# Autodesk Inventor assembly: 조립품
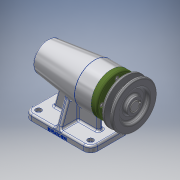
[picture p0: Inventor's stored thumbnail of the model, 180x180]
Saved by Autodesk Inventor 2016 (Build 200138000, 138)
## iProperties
Created: 2018-09
Part Number: 조립품
Document SubType Name: Assembly
Designer: CAMTIC
Author: CAMTIC
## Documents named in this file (12)
- C:\Users\CAMTIC\Desktop\480907V1023\조립품.iam
- C:\Users\CAMTIC\Desktop\480907V1023\본체.ipt
- C:\Users\CAMTIC\Desktop\480907V1023\베어링 51202.ipt
- C:\Users\CAMTIC\Desktop\480907V1023\어댑터슬리브.ipt
- C:\Users\CAMTIC\Desktop\480907V1023\베어링 6004.ipt
- C:\Users\CAMTIC\Desktop\480907V1023\축.ipt
- C:\Users\CAMTIC\Desktop\480907V1023\볼트 M4.ipt
- C:\Users\CAMTIC\Desktop\480907V1023\커버.ipt
- C:\Users\CAMTIC\Desktop\480907V1023\오일 실.ipt
- C:\Users\CAMTIC\Desktop\480907V1023\키 5 x 5 x 16.ipt
- C:\Users\CAMTIC\Desktop\480907V1023\V벨트풀리.ipt
- C:\Users\CAMTIC\Desktop\480907V1023\멈춤나사 M3.ipt
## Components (1 placed, 1 different names)
1. V벨트풀리:1
